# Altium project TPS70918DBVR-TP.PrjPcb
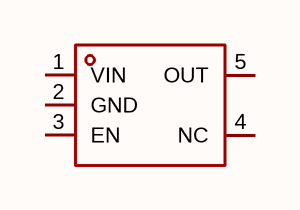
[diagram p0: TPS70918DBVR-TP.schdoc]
1 sheet, 1 parts. Net scope: global (net labels, ports and power ports of the same name join across sheets).

## Sheet TPS70918DBVR-TP.schdoc
size 127 x 101 mm

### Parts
U?  tps70918dbvr-tp  [SOT-23-5_L3.0-W1.6-P0.95-LS2.8-BR]  (value not drawn)

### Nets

Not connected (* = marked no-connect by the designer): U? 1(VIN) 2(GND) 3(EN) 4(NC) 5(OUT)

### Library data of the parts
U? = tps70918dbvr-tp: 输出极性:正极;工作电压:30V;输出电压:1.8V;输出电流:200mA;电源纹波抑制比(PSRR):80dB@(1kHz);输出类型:固定;; Manufacturer: TECH PUBLIC(台舟); AddInBom: yes; ModelId: 72410e292833493f86746b22636ce101; ModelTransform: 110.236,116.1415,0,0,0,0,0.002,0.001,0; Output Configuration: 正极; Voltage - Supply: 30V; Output Voltage: 1.8V; Output Current: 200mA; Voltage Dropout: 520mV@(100mA); standby current: 1.5uA; Output Type: 固定; Number of Outputs: 1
